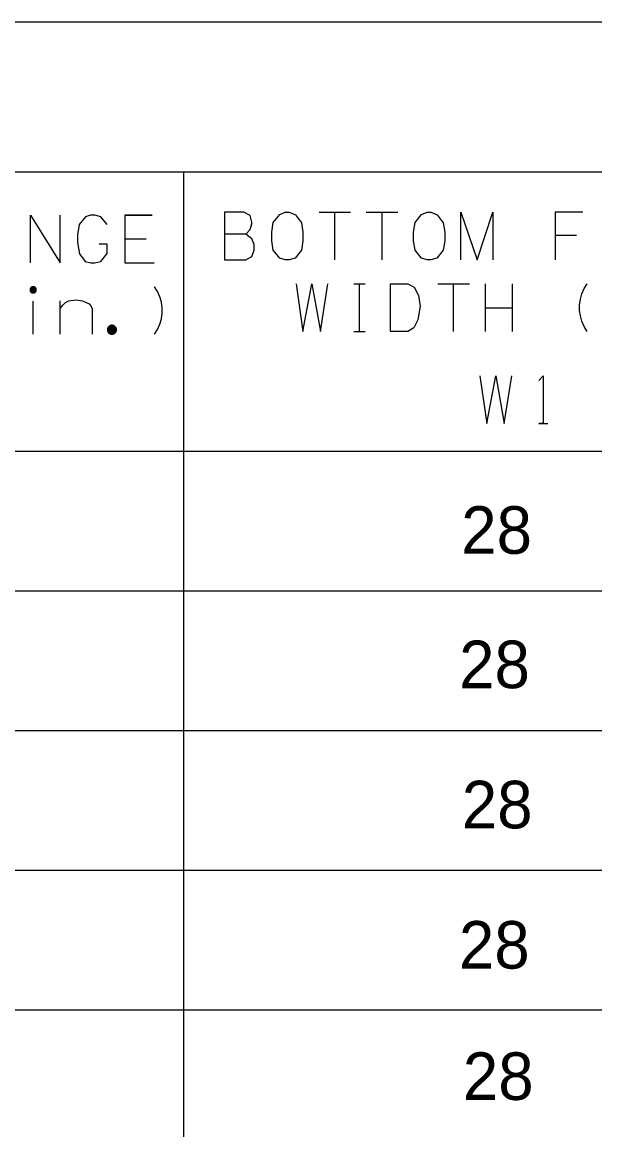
# Model space of a CAD drawing. Extents: x 635698 to 639877, y 296617 to 300175.
# Drawn here: x 639068.2 to 639104.3, y 299101 to 299170.8 of the extents above; entities that cross this region are included whole.
import ezdxf

# ---------------------------------------------------------------- set-up
doc = ezdxf.new("R2010")
doc.units = 0
for name, color, linetype in [('1', 7, 'Continuous'), ('2', 7, 'Continuous'), ('3', 7, 'Continuous')]:
    doc.layers.add(name, color=color, linetype=linetype)

msp = doc.modelspace()

# ---------------------------------------------------------------- linework, layer by layer
at = {"layer": '1'}
for p, q in [((639412.368, 299170.796), (638860.564, 299170.796)), ((639412.368, 299161.344), (639008.767, 299161.344)), ((639078.345, 299161.344), (639078.345, 299029.334)), ((639412.368, 299143.742), (639008.767, 299143.742))]:
    msp.add_line(p, q, dxfattribs=at)
for points in [[(639068.696, 299155.629), (639068.696, 299158.629), (639070.562, 299155.629), (639070.562, 299158.629)], [(639073.538, 299158.038), (639073.137, 299158.534), (639072.759, 299158.629), (639072.476, 299158.629), (639072.169, 299158.534), (639071.767, 299158.038), (639071.673, 299157.4), (639071.673, 299156.904), (639071.791, 299156.196), (639072.145, 299155.723), (639072.499, 299155.629), (639072.759, 299155.629), (639073.137, 299155.723), (639073.538, 299156.219), (639073.538, 299156.81), (639073.019, 299156.81)], [(639076.374, 299158.629), (639074.649, 299158.629), (639074.649, 299155.629), (639076.492, 299155.629)], [(639074.649, 299158.629), (639076.374, 299158.629)], [(639082.277, 299157.444), (639082.537, 299157.727), (639082.655, 299158.081), (639082.655, 299158.2), (639082.537, 299158.601), (639082.136, 299158.814), (639080.93, 299158.814), (639080.93, 299155.813), (639082.277, 299155.813), (639082.655, 299156.026), (639082.797, 299156.427), (639082.797, 299156.782), (639082.655, 299157.136), (639082.277, 299157.444), (639080.93, 299157.444)], [(639084.758, 299158.814), (639084.994, 299158.814), (639085.396, 299158.649), (639085.774, 299158.153), (639085.868, 299157.562), (639085.868, 299157.018), (639085.774, 299156.427), (639085.372, 299155.931), (639084.994, 299155.813), (639084.758, 299155.813), (639084.404, 299155.931), (639084.002, 299156.427), (639083.908, 299157.018), (639083.908, 299157.562), (639084.002, 299158.176), (639084.404, 299158.672), (639084.758, 299158.814)], [(639086.885, 299158.814), (639088.869, 299158.814)], [(639087.877, 299155.813), (639087.877, 299158.814)], [(639087.877, 299155.813), (639087.877, 299158.814)], [(639089.862, 299158.814), (639091.847, 299158.814)], [(639090.854, 299155.813), (639090.854, 299158.814)], [(639090.854, 299155.813), (639090.854, 299158.814)], [(639093.69, 299158.814), (639093.926, 299158.814), (639094.328, 299158.649), (639094.705, 299158.153), (639094.8, 299157.562), (639094.8, 299157.018), (639094.705, 299156.427), (639094.304, 299155.931), (639093.926, 299155.813), (639093.69, 299155.813), (639093.335, 299155.931), (639092.934, 299156.427), (639092.839, 299157.018), (639092.839, 299157.562), (639092.934, 299158.176), (639093.335, 299158.672), (639093.69, 299158.814)], [(639095.816, 299155.813), (639095.816, 299158.814), (639096.856, 299155.813), (639097.825, 299158.814), (639097.825, 299155.813)], [(639103.496, 299158.814), (639101.771, 299158.814), (639101.771, 299155.813)], [(639074.649, 299157.14), (639075.999, 299157.14)], [(639074.649, 299157.14), (639075.999, 299157.14)], [(639103.097, 299157.349), (639101.771, 299157.349)], [(639069.068, 299153.927), (639069.067, 299153.948), (639069.064, 299153.968), (639069.058, 299153.989), (639069.051, 299154.008), (639069.041, 299154.026), (639069.03, 299154.044), (639069.017, 299154.06), (639069.002, 299154.075), (639068.986, 299154.087), (639068.969, 299154.099), (639068.951, 299154.108), (639068.931, 299154.116), (639068.911, 299154.121), (639068.89, 299154.124), (639068.87, 299154.125), (639068.849, 299154.124), (639068.829, 299154.121), (639068.809, 299154.116), (639068.789, 299154.108), (639068.771, 299154.099), (639068.753, 299154.087), (639068.737, 299154.075), (639068.723, 299154.06), (639068.71, 299154.044), (639068.699, 299154.026), (639068.689, 299154.008), (639068.682, 299153.989), (639068.676, 299153.968), (639068.673, 299153.948), (639068.672, 299153.927), (639068.673, 299153.907), (639068.676, 299153.886), (639068.682, 299153.866), (639068.689, 299153.847), (639068.699, 299153.829), (639068.71, 299153.811), (639068.723, 299153.795), (639068.737, 299153.78), (639068.753, 299153.767), (639068.771, 299153.756), (639068.789, 299153.747), (639068.809, 299153.739), (639068.829, 299153.734), (639068.849, 299153.73), (639068.87, 299153.729), (639068.89, 299153.73), (639068.911, 299153.734), (639068.931, 299153.739), (639068.951, 299153.747), (639068.969, 299153.756), (639068.986, 299153.767), (639069.002, 299153.78), (639069.017, 299153.795), (639069.03, 299153.811), (639069.041, 299153.829), (639069.051, 299153.847), (639069.058, 299153.866), (639069.064, 299153.886), (639069.067, 299153.907), (639069.068, 299153.927)], [(639069.008, 299153.927), (639069.007, 299153.942), (639069.005, 299153.956), (639069.001, 299153.97), (639068.996, 299153.983), (639068.989, 299153.996), (639068.982, 299154.008), (639068.972, 299154.02), (639068.962, 299154.03), (639068.951, 299154.039), (639068.939, 299154.047), (639068.926, 299154.053), (639068.912, 299154.059), (639068.899, 299154.062), (639068.884, 299154.065), (639068.87, 299154.065), (639068.855, 299154.065), (639068.841, 299154.062), (639068.827, 299154.059), (639068.814, 299154.053), (639068.801, 299154.047), (639068.789, 299154.039), (639068.778, 299154.03), (639068.767, 299154.02), (639068.758, 299154.008), (639068.75, 299153.996), (639068.744, 299153.983), (639068.738, 299153.97), (639068.735, 299153.956), (639068.733, 299153.942), (639068.732, 299153.927), (639068.733, 299153.913), (639068.735, 299153.899), (639068.738, 299153.885), (639068.744, 299153.871), (639068.75, 299153.858), (639068.758, 299153.846), (639068.767, 299153.835), (639068.778, 299153.825), (639068.789, 299153.816), (639068.801, 299153.808), (639068.814, 299153.801), (639068.827, 299153.796), (639068.841, 299153.792), (639068.855, 299153.79), (639068.87, 299153.789), (639068.884, 299153.79), (639068.899, 299153.792), (639068.912, 299153.796), (639068.926, 299153.801), (639068.939, 299153.808), (639068.951, 299153.816), (639068.962, 299153.825), (639068.972, 299153.835), (639068.982, 299153.846), (639068.989, 299153.858), (639068.996, 299153.871), (639069.001, 299153.885), (639069.005, 299153.899), (639069.007, 299153.913), (639069.008, 299153.927)], [(639068.948, 299153.927), (639068.948, 299153.935), (639068.946, 299153.944), (639068.944, 299153.952), (639068.941, 299153.959), (639068.937, 299153.966), (639068.933, 299153.973), (639068.928, 299153.979), (639068.922, 299153.985), (639068.916, 299153.99), (639068.909, 299153.995), (639068.901, 299153.998), (639068.894, 299154.001), (639068.886, 299154.004), (639068.878, 299154.005), (639068.87, 299154.005), (639068.862, 299154.005), (639068.853, 299154.004), (639068.846, 299154.001), (639068.838, 299153.998), (639068.831, 299153.995), (639068.824, 299153.99), (639068.818, 299153.985), (639068.812, 299153.979), (639068.807, 299153.973), (639068.802, 299153.966), (639068.799, 299153.959), (639068.796, 299153.952), (639068.793, 299153.944), (639068.792, 299153.935), (639068.792, 299153.927), (639068.792, 299153.919), (639068.793, 299153.911), (639068.796, 299153.903), (639068.799, 299153.896), (639068.802, 299153.888), (639068.807, 299153.882), (639068.812, 299153.875), (639068.818, 299153.87), (639068.824, 299153.864), (639068.831, 299153.86), (639068.838, 299153.856), (639068.846, 299153.853), (639068.853, 299153.851), (639068.862, 299153.85), (639068.87, 299153.849), (639068.878, 299153.85), (639068.886, 299153.851), (639068.894, 299153.853), (639068.901, 299153.856), (639068.909, 299153.86), (639068.916, 299153.864), (639068.922, 299153.87), (639068.928, 299153.875), (639068.933, 299153.882), (639068.937, 299153.888), (639068.941, 299153.896), (639068.944, 299153.903), (639068.946, 299153.911), (639068.948, 299153.919), (639068.948, 299153.927)], [(639076.524, 299151.126), (639076.713, 299151.433), (639076.855, 299151.763), (639076.949, 299152.094), (639076.997, 299152.448), (639076.997, 299152.803), (639076.949, 299153.157), (639076.855, 299153.488), (639076.713, 299153.818), (639076.524, 299154.126)], [(639085.438, 299154.311), (639085.863, 299151.31), (639086.43, 299154.311), (639086.974, 299151.31), (639087.446, 299154.311)], [(639089.076, 299154.311), (639089.785, 299154.311)], [(639089.431, 299151.31), (639089.431, 299154.311)], [(639091.392, 299154.311), (639092.479, 299154.311), (639092.881, 299154.098), (639093.14, 299153.578), (639093.258, 299152.893), (639093.117, 299152.043), (639092.857, 299151.523), (639092.479, 299151.31), (639091.392, 299151.31), (639091.392, 299154.311)], [(639094.369, 299154.311), (639096.354, 299154.311)], [(639095.362, 299151.31), (639095.362, 299154.311)], [(639095.362, 299151.31), (639095.362, 299154.311)], [(639097.346, 299154.311), (639097.346, 299151.31)], [(639099.047, 299154.311), (639099.047, 299151.31)], [(639103.773, 299151.31), (639103.584, 299151.617), (639103.443, 299151.948), (639103.348, 299152.279), (639103.301, 299152.633), (639103.301, 299152.988), (639103.348, 299153.343), (639103.443, 299153.673), (639103.584, 299154.004), (639103.773, 299154.311)], [(639068.888, 299153.927), (639068.888, 299153.929), (639068.888, 299153.931), (639068.887, 299153.933), (639068.886, 299153.935), (639068.885, 299153.936), (639068.884, 299153.938), (639068.883, 299153.94), (639068.882, 299153.941), (639068.881, 299153.942), (639068.879, 299153.943), (639068.877, 299153.944), (639068.875, 299153.945), (639068.874, 299153.945), (639068.872, 299153.945), (639068.87, 299153.945), (639068.868, 299153.945), (639068.866, 299153.945), (639068.864, 299153.945), (639068.863, 299153.944), (639068.861, 299153.943), (639068.859, 299153.942), (639068.858, 299153.941), (639068.856, 299153.94), (639068.855, 299153.938), (639068.854, 299153.936), (639068.853, 299153.935), (639068.853, 299153.933), (639068.852, 299153.931), (639068.852, 299153.929), (639068.852, 299153.927), (639068.852, 299153.926), (639068.852, 299153.924), (639068.853, 299153.922), (639068.853, 299153.92), (639068.854, 299153.918), (639068.855, 299153.917), (639068.856, 299153.915), (639068.858, 299153.914), (639068.859, 299153.913), (639068.861, 299153.912), (639068.863, 299153.911), (639068.864, 299153.91), (639068.866, 299153.91), (639068.868, 299153.909), (639068.87, 299153.909), (639068.872, 299153.909), (639068.874, 299153.91), (639068.875, 299153.91), (639068.877, 299153.911), (639068.879, 299153.912), (639068.881, 299153.913), (639068.882, 299153.914), (639068.883, 299153.915), (639068.884, 299153.917), (639068.885, 299153.918), (639068.886, 299153.92), (639068.887, 299153.922), (639068.888, 299153.924), (639068.888, 299153.926), (639068.888, 299153.927)], [(639070.571, 299152.756), (639070.736, 299152.968), (639070.902, 299153.133), (639071.114, 299153.228), (639071.587, 299153.299), (639071.988, 299153.228), (639072.39, 299153.039), (639072.508, 299152.921), (639072.579, 299152.732), (639072.579, 299151.126)], [(639068.87, 299151.126), (639068.87, 299153.204)], [(639070.571, 299151.126), (639070.571, 299153.228)], [(639097.346, 299152.799), (639099.047, 299152.799)], [(639074.117, 299151.41), (639074.116, 299151.44), (639074.111, 299151.47), (639074.103, 299151.498), (639074.093, 299151.526), (639074.079, 299151.553), (639074.063, 299151.578), (639074.044, 299151.601), (639074.023, 299151.622), (639074, 299151.641), (639073.975, 299151.657), (639073.948, 299151.671), (639073.92, 299151.681), (639073.892, 299151.689), (639073.862, 299151.694), (639073.832, 299151.695), (639073.802, 299151.694), (639073.773, 299151.689), (639073.744, 299151.681), (639073.716, 299151.671), (639073.69, 299151.657), (639073.665, 299151.641), (639073.642, 299151.622), (639073.62, 299151.601), (639073.602, 299151.578), (639073.586, 299151.553), (639073.572, 299151.526), (639073.561, 299151.498), (639073.554, 299151.47), (639073.549, 299151.44), (639073.548, 299151.41), (639073.549, 299151.38), (639073.554, 299151.351), (639073.561, 299151.322), (639073.572, 299151.294), (639073.586, 299151.268), (639073.602, 299151.243), (639073.62, 299151.22), (639073.642, 299151.198), (639073.665, 299151.18), (639073.69, 299151.164), (639073.716, 299151.15), (639073.744, 299151.139), (639073.773, 299151.132), (639073.802, 299151.127), (639073.832, 299151.126), (639073.862, 299151.127), (639073.892, 299151.132), (639073.92, 299151.139), (639073.948, 299151.15), (639073.975, 299151.164), (639074, 299151.18), (639074.023, 299151.198), (639074.044, 299151.22), (639074.063, 299151.243), (639074.079, 299151.268), (639074.093, 299151.294), (639074.103, 299151.322), (639074.111, 299151.351), (639074.116, 299151.38), (639074.117, 299151.41)], [(639074.057, 299151.41), (639074.056, 299151.434), (639074.053, 299151.457), (639074.046, 299151.48), (639074.038, 299151.502), (639074.027, 299151.523), (639074.014, 299151.543), (639073.999, 299151.561), (639073.983, 299151.577), (639073.965, 299151.592), (639073.945, 299151.605), (639073.924, 299151.616), (639073.902, 299151.624), (639073.879, 299151.631), (639073.856, 299151.634), (639073.832, 299151.635), (639073.809, 299151.634), (639073.786, 299151.631), (639073.763, 299151.624), (639073.741, 299151.616), (639073.72, 299151.605), (639073.7, 299151.592), (639073.682, 299151.577), (639073.665, 299151.561), (639073.65, 299151.543), (639073.638, 299151.523), (639073.627, 299151.502), (639073.618, 299151.48), (639073.612, 299151.457), (639073.609, 299151.434), (639073.607, 299151.41), (639073.609, 299151.387), (639073.612, 299151.364), (639073.618, 299151.341), (639073.627, 299151.319), (639073.638, 299151.298), (639073.65, 299151.278), (639073.665, 299151.26), (639073.682, 299151.243), (639073.7, 299151.228), (639073.72, 299151.216), (639073.741, 299151.205), (639073.763, 299151.196), (639073.786, 299151.19), (639073.809, 299151.187), (639073.832, 299151.185), (639073.856, 299151.187), (639073.879, 299151.19), (639073.902, 299151.196), (639073.924, 299151.205), (639073.945, 299151.216), (639073.965, 299151.228), (639073.983, 299151.243), (639073.999, 299151.26), (639074.014, 299151.278), (639074.027, 299151.298), (639074.038, 299151.319), (639074.046, 299151.341), (639074.053, 299151.364), (639074.056, 299151.387), (639074.057, 299151.41)], [(639073.997, 299151.41), (639073.997, 299151.428), (639073.994, 299151.445), (639073.989, 299151.461), (639073.983, 299151.477), (639073.975, 299151.493), (639073.966, 299151.507), (639073.955, 299151.521), (639073.943, 299151.533), (639073.93, 299151.544), (639073.915, 299151.553), (639073.899, 299151.561), (639073.883, 299151.567), (639073.867, 299151.572), (639073.85, 299151.575), (639073.832, 299151.575), (639073.815, 299151.575), (639073.798, 299151.572), (639073.782, 299151.567), (639073.765, 299151.561), (639073.75, 299151.553), (639073.735, 299151.544), (639073.722, 299151.533), (639073.71, 299151.521), (639073.699, 299151.507), (639073.69, 299151.493), (639073.682, 299151.477), (639073.675, 299151.461), (639073.671, 299151.445), (639073.668, 299151.428), (639073.667, 299151.41), (639073.668, 299151.393), (639073.671, 299151.376), (639073.675, 299151.36), (639073.682, 299151.343), (639073.69, 299151.328), (639073.699, 299151.313), (639073.71, 299151.3), (639073.722, 299151.288), (639073.735, 299151.277), (639073.75, 299151.268), (639073.765, 299151.26), (639073.782, 299151.253), (639073.798, 299151.249), (639073.815, 299151.246), (639073.832, 299151.245), (639073.85, 299151.246), (639073.867, 299151.249), (639073.883, 299151.253), (639073.899, 299151.26), (639073.915, 299151.268), (639073.93, 299151.277), (639073.943, 299151.288), (639073.955, 299151.3), (639073.966, 299151.313), (639073.975, 299151.328), (639073.983, 299151.343), (639073.989, 299151.36), (639073.994, 299151.376), (639073.997, 299151.393), (639073.997, 299151.41)], [(639073.937, 299151.41), (639073.937, 299151.421), (639073.935, 299151.432), (639073.932, 299151.443), (639073.928, 299151.453), (639073.923, 299151.463), (639073.917, 299151.472), (639073.91, 299151.481), (639073.903, 299151.488), (639073.894, 299151.495), (639073.885, 299151.501), (639073.875, 299151.506), (639073.865, 299151.51), (639073.854, 299151.513), (639073.843, 299151.515), (639073.832, 299151.515), (639073.821, 299151.515), (639073.811, 299151.513), (639073.8, 299151.51), (639073.79, 299151.506), (639073.78, 299151.501), (639073.771, 299151.495), (639073.762, 299151.488), (639073.754, 299151.481), (639073.748, 299151.472), (639073.741, 299151.463), (639073.737, 299151.453), (639073.732, 299151.443), (639073.73, 299151.432), (639073.728, 299151.421), (639073.727, 299151.41), (639073.728, 299151.399), (639073.73, 299151.388), (639073.732, 299151.378), (639073.737, 299151.368), (639073.741, 299151.358), (639073.748, 299151.349), (639073.754, 299151.34), (639073.762, 299151.332), (639073.771, 299151.325), (639073.78, 299151.319), (639073.79, 299151.315), (639073.8, 299151.31), (639073.811, 299151.308), (639073.821, 299151.306), (639073.832, 299151.305), (639073.843, 299151.306), (639073.854, 299151.308), (639073.865, 299151.31), (639073.875, 299151.315), (639073.885, 299151.319), (639073.894, 299151.325), (639073.903, 299151.332), (639073.91, 299151.34), (639073.917, 299151.349), (639073.923, 299151.358), (639073.928, 299151.368), (639073.932, 299151.378), (639073.935, 299151.388), (639073.937, 299151.399), (639073.937, 299151.41)], [(639073.878, 299151.41), (639073.877, 299151.415), (639073.876, 299151.42), (639073.875, 299151.424), (639073.873, 299151.429), (639073.871, 299151.433), (639073.869, 299151.437), (639073.866, 299151.44), (639073.863, 299151.444), (639073.859, 299151.447), (639073.855, 299151.449), (639073.851, 299151.451), (639073.846, 299151.453), (639073.842, 299151.454), (639073.837, 299151.455), (639073.832, 299151.455), (639073.828, 299151.455), (639073.823, 299151.454), (639073.819, 299151.453), (639073.814, 299151.451), (639073.81, 299151.449), (639073.806, 299151.447), (639073.802, 299151.444), (639073.799, 299151.44), (639073.796, 299151.437), (639073.793, 299151.433), (639073.791, 299151.429), (639073.79, 299151.424), (639073.789, 299151.42), (639073.788, 299151.415), (639073.787, 299151.41), (639073.788, 299151.406), (639073.789, 299151.401), (639073.79, 299151.397), (639073.791, 299151.392), (639073.793, 299151.388), (639073.796, 299151.384), (639073.799, 299151.38), (639073.802, 299151.377), (639073.806, 299151.374), (639073.81, 299151.371), (639073.814, 299151.369), (639073.819, 299151.368), (639073.823, 299151.367), (639073.828, 299151.366), (639073.832, 299151.365), (639073.837, 299151.366), (639073.842, 299151.367), (639073.846, 299151.368), (639073.851, 299151.369), (639073.855, 299151.371), (639073.859, 299151.374), (639073.863, 299151.377), (639073.866, 299151.38), (639073.869, 299151.384), (639073.871, 299151.388), (639073.873, 299151.392), (639073.875, 299151.397), (639073.876, 299151.401), (639073.877, 299151.406), (639073.878, 299151.41)], [(639089.076, 299151.31), (639089.785, 299151.31)], [(639097.021, 299148.503), (639097.446, 299145.502), (639098.013, 299148.503), (639098.556, 299145.502), (639099.029, 299148.503)], [(639100.73, 299148.219), (639101.014, 299148.503), (639101.014, 299145.502), (639100.73, 299145.502), (639101.297, 299145.502)]]:
    msp.add_lwpolyline(points, dxfattribs=at)
at = {"layer": '2'}
for p, q in [((639412.368, 299134.941), (639008.767, 299134.941)), ((639412.368, 299126.141), (639008.767, 299126.141)), ((639412.368, 299117.341), (639008.767, 299117.341)), ((639412.368, 299108.539), (639008.767, 299108.539))]:
    msp.add_line(p, q, dxfattribs=at)

# ---------------------------------------------------------------- texts
at = {"layer": '3'}
for p in [(639095.841, 299137.292), (639095.709, 299128.822), (639095.878, 299119.989), (639095.695, 299111.149), (639095.945, 299102.873)]:
    msp.add_text('28', height=2.9989, dxfattribs=at).set_placement(p)

doc.saveas('drawing.dxf')
